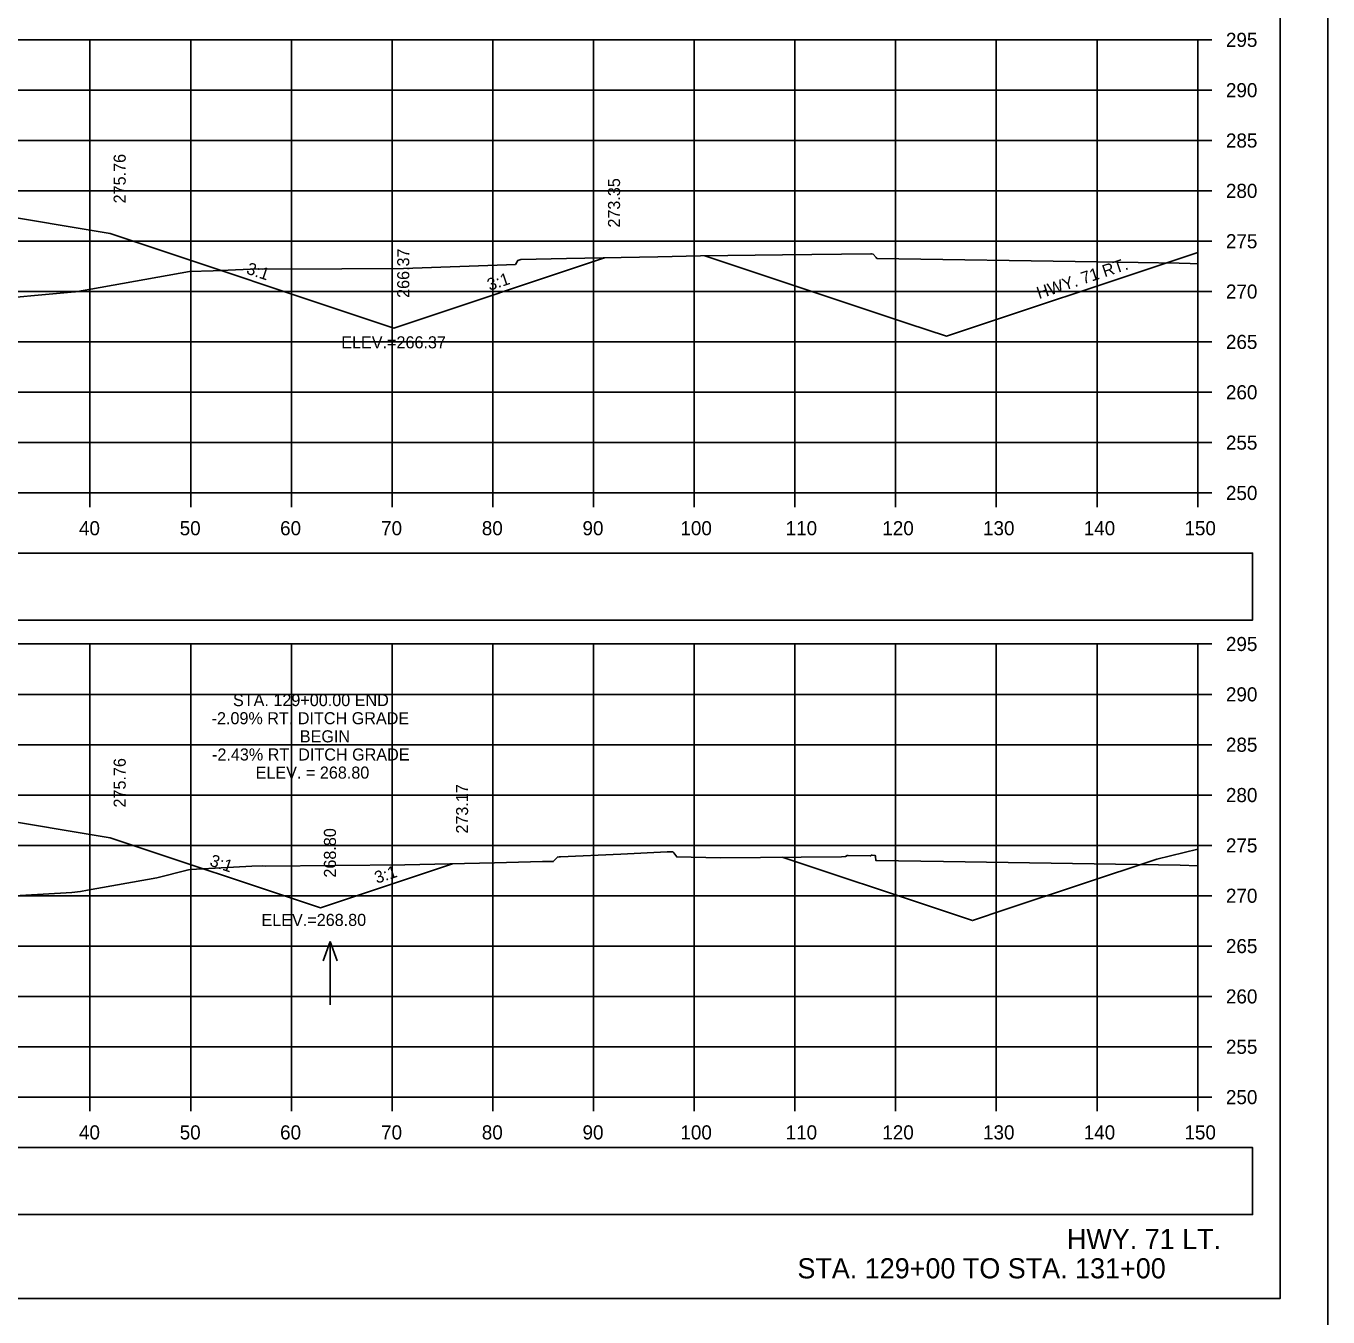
# Model space of a CAD drawing. Extents: x 285 to 4233, y -659 to 3710.
# Drawn here: x 572.9 to 702.2, y 1685 to 1813.2 of the extents above; entities that cross this region are included whole.
import ezdxf

# ---------------------------------------------------------------- set-up
doc = ezdxf.new("R2010")
doc.units = 0
for name, color, linetype in [('R_Axis', 7, 'Continuous'), ('R_Axis Annot', 7, 'Continuous'), ('R_Border', 7, 'Continuous'), ('R_Draft', 7, 'Continuous'), ('R_Exist Surface', 7, 'Continuous'), ('R_Fin Surface', 7, 'Continuous'), ('R_Grid', 7, 'Continuous'), ('R_No Plot', 7, 'Continuous'), ('R_Water', 7, 'Continuous'), ('R_Water Annot', 7, 'Continuous'), ('R_Xsect Elev', 7, 'Continuous'), ('R_Xsect Slope', 7, 'Continuous')]:
    doc.layers.add(name, color=color, linetype=linetype)

msp = doc.modelspace()

# ---------------------------------------------------------------- linework, layer by layer
at = {"layer": 'R_Axis'}
for p, q in [((689.28, 1766.86), (689.28, 1811.86)), ((690.68, 1811.86), (689.28, 1811.86)), ((690.68, 1806.86), (689.28, 1806.86)), ((690.68, 1801.86), (689.28, 1801.86)), ((690.68, 1796.86), (689.28, 1796.86)), ((690.68, 1791.86), (689.28, 1791.86)), ((690.68, 1786.86), (689.28, 1786.86)), ((690.68, 1781.86), (689.28, 1781.86)), ((690.68, 1776.86), (689.28, 1776.86)), ((690.68, 1771.86), (689.28, 1771.86)), ((389.28, 1766.86), (689.28, 1766.86)), ((579.28, 1765.46), (579.28, 1766.86)), ((589.28, 1765.46), (589.28, 1766.86)), ((599.28, 1765.46), (599.28, 1766.86)), ((609.28, 1765.46), (609.28, 1766.86)), ((619.28, 1765.46), (619.28, 1766.86)), ((629.28, 1765.46), (629.28, 1766.86)), ((639.28, 1765.46), (639.28, 1766.86)), ((649.28, 1765.46), (649.28, 1766.86)), ((659.28, 1765.46), (659.28, 1766.86)), ((669.28, 1765.46), (669.28, 1766.86)), ((679.28, 1765.46), (679.28, 1766.86)), ((689.28, 1765.46), (689.28, 1766.86)), ((690.68, 1766.86), (689.28, 1766.86)), ((689.28, 1706.86), (689.28, 1751.86)), ((690.68, 1751.86), (689.28, 1751.86)), ((690.68, 1746.86), (689.28, 1746.86)), ((690.68, 1741.86), (689.28, 1741.86)), ((690.68, 1736.86), (689.28, 1736.86)), ((690.68, 1731.86), (689.28, 1731.86)), ((690.68, 1726.86), (689.28, 1726.86)), ((690.68, 1721.86), (689.28, 1721.86)), ((690.68, 1716.86), (689.28, 1716.86)), ((690.68, 1711.86), (689.28, 1711.86)), ((389.28, 1706.86), (689.28, 1706.86)), ((579.28, 1705.46), (579.28, 1706.86)), ((589.28, 1705.46), (589.28, 1706.86)), ((599.28, 1705.46), (599.28, 1706.86)), ((609.28, 1705.46), (609.28, 1706.86)), ((619.28, 1705.46), (619.28, 1706.86)), ((629.28, 1705.46), (629.28, 1706.86)), ((639.28, 1705.46), (639.28, 1706.86)), ((649.28, 1705.46), (649.28, 1706.86)), ((659.28, 1705.46), (659.28, 1706.86)), ((669.28, 1705.46), (669.28, 1706.86)), ((679.28, 1705.46), (679.28, 1706.86)), ((689.28, 1705.46), (689.28, 1706.86)), ((690.68, 1706.86), (689.28, 1706.86))]:
    msp.add_line(p, q, dxfattribs=at)
at = {"layer": 'R_Axis Annot'}
for points in [[(554.36, 1754.24), (694.72, 1754.24), (694.72, 1760.89), (554.36, 1760.89)], [(554.36, 1695.2), (694.72, 1695.2), (694.72, 1701.85), (554.36, 1701.85)]]:
    msp.add_lwpolyline(points, close=True, dxfattribs=at)
at = {"layer": 'R_Border'}
for q in [(697.46, 1892.32), (381.28, 1686.86)]:
    msp.add_line((697.46, 1686.86), q, dxfattribs=at)
at = {"layer": 'R_Exist Surface'}
for points in [[(568.68, 1786), (577.42, 1786.8), (577.84, 1786.83), (579.37, 1787.11), (589.18, 1788.84), (591.53, 1788.93), (595.22, 1789.07), (604.29, 1789.12), (610.43, 1789.15), (620.63, 1789.5), (621.5, 1789.54), (621.52, 1789.56), (621.76, 1789.96), (621.78, 1789.96), (622.05, 1790.04), (626.6, 1790.13), (635.68, 1790.32), (639.89, 1790.4), (648.04, 1790.5), (656.82, 1790.61), (656.88, 1790.6), (657.05, 1790.59), (657.34, 1790.23), (657.42, 1790.13), (679.31, 1789.81), (687.45, 1789.69), (688.52, 1789.66), (689.28, 1789.63)], [(572.35, 1726.87), (577.49, 1727.19), (578.33, 1727.27), (579.04, 1727.4), (585.93, 1728.64), (588.92, 1729.4), (589.08, 1729.43), (589.27, 1729.45), (595.34, 1729.8), (596.41, 1729.82), (596.7, 1729.81), (610.53, 1729.93), (619.46, 1730.12), (624.23, 1730.26), (625.28, 1730.25), (625.6, 1730.59), (625.7, 1730.7), (625.86, 1730.72), (625.92, 1730.73), (625.95, 1730.73), (626.01, 1730.72), (631.98, 1730.99), (636.61, 1731.21), (636.63, 1731.22), (636.79, 1731.23), (636.86, 1731.23), (637.17, 1731.22), (637.26, 1731.11), (637.54, 1730.72), (641.86, 1730.64), (653.91, 1730.72), (654.31, 1730.74), (654.46, 1730.86), (654.47, 1730.86), (654.51, 1730.87), (654.52, 1730.87), (654.56, 1730.85), (656.75, 1730.81), (656.76, 1730.81), (656.76, 1730.81), (656.78, 1730.82), (656.9, 1730.9), (656.95, 1730.89), (657.26, 1730.84), (657.29, 1730.74), (657.32, 1730.35), (664.02, 1730.25), (687.53, 1729.89), (689.28, 1729.83)]]:
    msp.add_lwpolyline(points, dxfattribs=at)
at = {"layer": 'R_Fin Surface'}
for points in [[(460.61, 1783.92), (465.8, 1782.19), (497.28, 1792.68), (517.28, 1796.02), (525.28, 1796.34), (527.28, 1796.38), (551.28, 1796.86), (557.28, 1796.62), (581.28, 1792.62), (609.44, 1783.23), (630.37, 1790.21)], [(640.34, 1790.41), (660.51, 1783.69), (664.34, 1782.42), (687.61, 1790.17), (689.28, 1790.73)], [(463.79, 1724.04), (467.57, 1722.78), (497.28, 1732.68), (517.28, 1736.02), (525.28, 1736.34), (527.28, 1736.38), (551.28, 1736.86), (557.28, 1736.62), (581.28, 1732.62), (602.16, 1725.66), (615.28, 1730.03)], [(648.03, 1730.68), (663.73, 1725.45), (666.91, 1724.39), (670.25, 1725.51), (685.22, 1730.5), (689.28, 1731.48)]]:
    msp.add_lwpolyline(points, dxfattribs=at)
at = {"layer": 'R_Grid'}
for p, q in [((389.28, 1811.86), (689.28, 1811.86)), ((579.28, 1766.86), (579.28, 1811.86)), ((589.28, 1766.86), (589.28, 1811.86)), ((599.28, 1766.86), (599.28, 1811.86)), ((609.28, 1766.86), (609.28, 1811.86)), ((619.28, 1766.86), (619.28, 1811.86)), ((629.28, 1766.86), (629.28, 1811.86)), ((639.28, 1766.86), (639.28, 1811.86)), ((649.28, 1766.86), (649.28, 1811.86)), ((659.28, 1766.86), (659.28, 1811.86)), ((669.28, 1766.86), (669.28, 1811.86)), ((679.28, 1766.86), (679.28, 1811.86)), ((689.28, 1766.86), (689.28, 1811.86)), ((389.28, 1806.86), (689.28, 1806.86)), ((389.28, 1801.86), (689.28, 1801.86)), ((389.28, 1796.86), (689.28, 1796.86)), ((389.28, 1791.86), (689.28, 1791.86)), ((389.28, 1786.86), (689.28, 1786.86)), ((389.28, 1781.86), (689.28, 1781.86)), ((389.28, 1776.86), (689.28, 1776.86)), ((389.28, 1771.86), (689.28, 1771.86)), ((389.28, 1766.86), (689.28, 1766.86)), ((389.28, 1751.86), (689.28, 1751.86)), ((579.28, 1706.86), (579.28, 1751.86)), ((589.28, 1706.86), (589.28, 1751.86)), ((599.28, 1706.86), (599.28, 1751.86)), ((609.28, 1706.86), (609.28, 1751.86)), ((619.28, 1706.86), (619.28, 1751.86)), ((629.28, 1706.86), (629.28, 1751.86)), ((639.28, 1706.86), (639.28, 1751.86)), ((649.28, 1706.86), (649.28, 1751.86)), ((659.28, 1706.86), (659.28, 1751.86)), ((669.28, 1706.86), (669.28, 1751.86)), ((679.28, 1706.86), (679.28, 1751.86)), ((689.28, 1706.86), (689.28, 1751.86)), ((389.28, 1746.86), (689.28, 1746.86)), ((389.28, 1741.86), (689.28, 1741.86)), ((389.28, 1736.86), (689.28, 1736.86)), ((389.28, 1731.86), (689.28, 1731.86)), ((389.28, 1726.86), (689.28, 1726.86)), ((389.28, 1721.86), (689.28, 1721.86)), ((389.28, 1716.86), (689.28, 1716.86)), ((389.28, 1711.86), (689.28, 1711.86)), ((389.28, 1706.86), (689.28, 1706.86))]:
    msp.add_line(p, q, dxfattribs=at)
at = {"layer": 'R_No Plot'}
for points in [[(368.87, 1896.21), (702.21, 1896.21), (702.21, 1682.87), (368.87, 1682.87)], [(615.2, 1892.32), (634.82, 1892.32), (634.82, 1882.44), (650.93, 1882.44), (674.13, 1882.44), (674.25, 1854.28), (697.46, 1854.28), (697.46, 1686.86), (381.28, 1686.86), (381.28, 1892.32)]]:
    msp.add_lwpolyline(points, close=True, dxfattribs=at)
at = {"layer": 'R_Water Annot'}
for p, q in [((603.14, 1722.32), (602.44, 1720.4)), ((603.14, 1716.04), (603.14, 1722.32)), ((603.14, 1722.32), (603.84, 1720.4))]:
    msp.add_line(p, q, dxfattribs=at)

# ---------------------------------------------------------------- texts
at = {"layer": 'R_Axis Annot'}
for s, p in [('295', (692.08, 1811.16)), ('290', (692.08, 1806.16)), ('285', (692.08, 1801.16)), ('280', (692.08, 1796.16)), ('275', (692.08, 1791.16)), ('270', (692.08, 1786.16)), ('265', (692.08, 1781.16)), ('260', (692.08, 1776.16)), ('255', (692.08, 1771.16)), ('250', (692.08, 1766.16)), ('40', (578.19, 1762.66)), ('50', (588.19, 1762.66)), ('60', (598.16, 1762.66)), ('70', (608.19, 1762.66)), ('80', (618.19, 1762.66)), ('90', (628.19, 1762.66)), ('100', (637.91, 1762.66)), ('110', (648.36, 1762.66)), ('120', (657.96, 1762.66)), ('130', (667.96, 1762.66)), ('140', (677.96, 1762.66)), ('150', (687.96, 1762.66)), ('295', (692.08, 1751.16)), ('290', (692.08, 1746.16)), ('285', (692.08, 1741.16)), ('280', (692.08, 1736.16)), ('275', (692.08, 1731.16)), ('270', (692.08, 1726.16)), ('265', (692.08, 1721.16)), ('260', (692.08, 1716.16)), ('255', (692.08, 1711.16)), ('250', (692.08, 1706.16)), ('40', (578.19, 1702.66)), ('50', (588.19, 1702.66)), ('60', (598.16, 1702.66)), ('70', (608.19, 1702.66)), ('80', (618.19, 1702.66)), ('90', (628.19, 1702.66)), ('100', (637.91, 1702.66)), ('110', (648.36, 1702.66)), ('120', (657.96, 1702.66)), ('130', (667.96, 1702.66)), ('140', (677.96, 1702.66)), ('150', (687.96, 1702.66))]:
    msp.add_text(s, height=1.4, dxfattribs=at).set_placement(p)
at = {"layer": 'R_Draft'}
for s, p in [('HWY. 71 LT.', (676.29, 1691.77)), ('STA. 129+00 TO STA. 131+00', (649.53, 1688.86))]:
    msp.add_text(s, height=2, dxfattribs=at).set_placement(p)
at = {"layer": 'R_Water'}
msp.add_text('HWY. 71 RT.', height=1.2, rotation=18.4331, dxfattribs=at).set_placement((673.52, 1786.11))
at = {"layer": 'R_Xsect Elev'}
for s, p in [('275.76', (582.83, 1795.62)), ('273.35', (631.92, 1793.21)), ('266.37', (610.99, 1786.23)), ('275.76', (582.83, 1735.62)), ('273.17', (616.83, 1733.03)), ('268.80', (603.71, 1728.66))]:
    msp.add_text(s, height=1.2, rotation=90, dxfattribs=at).set_placement(p)
for s, p in [('ELEV.=266.37', (604.23, 1781.22)), ('STA. 129+00.00 END', (593.48, 1745.69)), ('-2.09% RT. DITCH GRADE', (591.36, 1743.89)), ('BEGIN', (600.12, 1742.09)), ('-2.43% RT. DITCH GRADE', (591.4, 1740.29)), ('ELEV. = 268.80', (595.73, 1738.49)), ('ELEV.=268.80', (596.31, 1723.86))]:
    msp.add_text(s, height=1.2, dxfattribs=at).set_placement(p)
at = {"layer": 'R_Xsect Slope'}
for rotation, p in [(341.5651, (594.73, 1788.66)), (18.4349, (618.96, 1786.93)), (341.5651, (591.09, 1729.87)), (18.4349, (607.77, 1728.05))]:
    msp.add_text('3:1', height=1.2, rotation=rotation, dxfattribs=at).set_placement(p)

doc.saveas('drawing.dxf')
